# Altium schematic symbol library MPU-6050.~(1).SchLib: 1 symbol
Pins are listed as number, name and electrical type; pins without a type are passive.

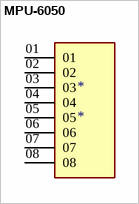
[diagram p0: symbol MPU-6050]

## MPU-6050
designator *
pins: 01, 02, 03, 04, 05, 06, 07, 08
